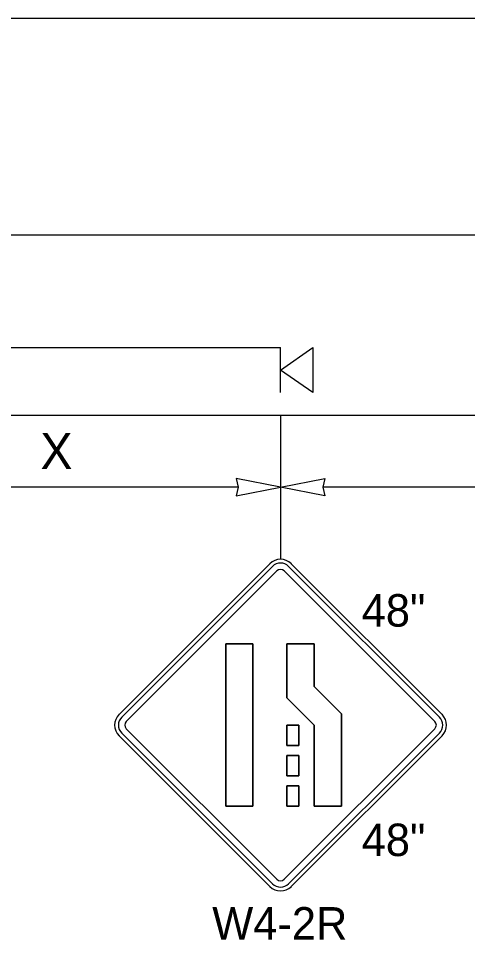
# Model space of a CAD drawing. Extents: x 99958 to 100176, y 99935 to 100011.
# Drawn here: x 100024.182 to 100025.178, y 99973.572 to 99975.616 of the extents above; entities that cross this region are included whole.
import ezdxf

# ---------------------------------------------------------------- set-up
doc = ezdxf.new("R2010")
doc.units = 0
for name, color, linetype in [('RD_ED_ShoulderPavedEdge', 7, 'Continuous'), ('RD_MK_LineEdgeWhite', 7, 'Continuous'), ('RD_MK_LineLane', 7, 'Continuous'), ('TR_SN_ConstructionSigns', 7, 'Continuous'), ('TR_WZ_PortableSignMountBlk-Org', 7, 'Continuous'), ('TR_WZ_WorkZoneDetails', 7, 'Continuous'), ('TR_WZ_WorkZoneTextCurrent', 7, 'Continuous')]:
    doc.layers.add(name, color=color, linetype=linetype)

msp = doc.modelspace()

# ---------------------------------------------------------------- linework, layer by layer
at = {"layer": 'RD_ED_ShoulderPavedEdge'}
msp.add_line((100021.7266, 99974.7357), (100034.8933, 99974.7357), dxfattribs=at)
at = {"layer": 'RD_MK_LineEdgeWhite'}
msp.add_line((100021.7266, 99975.1357), (100034.8933, 99975.1357), dxfattribs=at)
at = {"layer": 'RD_MK_LineLane'}
msp.add_lwpolyline([(100034.8933, 99975.6157), (100021.7266, 99975.6157)], dxfattribs=at)
at = {"layer": 'TR_SN_ConstructionSigns'}
for p, q in [((100024.7397, 99974.4058), (100024.4056, 99974.0717)), ((100024.7457, 99974.3999), (100024.4116, 99974.0658)), ((100025.1156, 99974.0658), (100024.7815, 99974.3999)), ((100025.1215, 99974.0717), (100024.7874, 99974.4058)), ((100024.4215, 99974.0558), (100024.7556, 99974.3899)), ((100024.7715, 99974.3899), (100025.1056, 99974.0558)), ((100024.6419, 99974.2279), (100024.7024, 99974.2279)), ((100024.6419, 99973.8679), (100024.6419, 99974.2279)), ((100024.7024, 99974.2279), (100024.6419, 99974.2279)), ((100024.6419, 99974.2279), (100024.6419, 99973.8679)), ((100024.7024, 99974.2279), (100024.7024, 99973.8679)), ((100024.7024, 99973.8679), (100024.7024, 99974.2279)), ((100024.7776, 99974.2279), (100024.8381, 99974.2279)), ((100024.7776, 99974.1083), (100024.7776, 99974.2279)), ((100024.8381, 99974.2279), (100024.7776, 99974.2279)), ((100024.7776, 99974.2279), (100024.7776, 99974.1083)), ((100024.8381, 99974.2279), (100024.8381, 99974.1334)), ((100024.8381, 99974.1334), (100024.8381, 99974.2279)), ((100024.8381, 99974.1334), (100024.8986, 99974.0729)), ((100024.8986, 99974.0729), (100024.8381, 99974.1334)), ((100024.8381, 99974.0479), (100024.7776, 99974.1083)), ((100024.7776, 99974.1083), (100024.8381, 99974.0479)), ((100024.8986, 99974.0729), (100024.8986, 99973.8679)), ((100024.8986, 99973.8679), (100024.8986, 99974.0729)), ((100024.7776, 99974.0479), (100024.8044, 99974.0479)), ((100024.7776, 99974.0029), (100024.7776, 99974.0479)), ((100024.8044, 99974.0479), (100024.7776, 99974.0479)), ((100024.7776, 99974.0479), (100024.7776, 99974.0029)), ((100024.8044, 99974.0479), (100024.8044, 99974.0029)), ((100024.8044, 99974.0029), (100024.8044, 99974.0479)), ((100024.8381, 99973.8679), (100024.8381, 99974.0479)), ((100024.8381, 99974.0479), (100024.8381, 99973.8679)), ((100024.4056, 99974.024), (100024.7397, 99973.6899)), ((100024.4116, 99974.03), (100024.7457, 99973.6959)), ((100024.7556, 99973.7058), (100024.4215, 99974.0399)), ((100025.1056, 99974.0399), (100024.7715, 99973.7058)), ((100024.7815, 99973.6959), (100025.1156, 99974.03)), ((100024.7874, 99973.6899), (100025.1215, 99974.024)), ((100024.8044, 99974.0029), (100024.7776, 99974.0029)), ((100024.7776, 99974.0029), (100024.8044, 99974.0029)), ((100024.7776, 99973.9804), (100024.8044, 99973.9804)), ((100024.7776, 99973.9354), (100024.7776, 99973.9804)), ((100024.8044, 99973.9804), (100024.7776, 99973.9804)), ((100024.7776, 99973.9804), (100024.7776, 99973.9354)), ((100024.8044, 99973.9804), (100024.8044, 99973.9354)), ((100024.8044, 99973.9354), (100024.8044, 99973.9804)), ((100024.8044, 99973.9354), (100024.7776, 99973.9354)), ((100024.7776, 99973.9354), (100024.8044, 99973.9354)), ((100024.7776, 99973.9129), (100024.8044, 99973.9129)), ((100024.7776, 99973.8679), (100024.7776, 99973.9129)), ((100024.8044, 99973.9129), (100024.7776, 99973.9129)), ((100024.7776, 99973.9129), (100024.7776, 99973.8679)), ((100024.8044, 99973.9129), (100024.8044, 99973.8679)), ((100024.8044, 99973.8679), (100024.8044, 99973.9129)), ((100024.7024, 99973.8679), (100024.6419, 99973.8679)), ((100024.6419, 99973.8679), (100024.7024, 99973.8679)), ((100024.8044, 99973.8679), (100024.7776, 99973.8679)), ((100024.7776, 99973.8679), (100024.8044, 99973.8679)), ((100024.8986, 99973.8679), (100024.8381, 99973.8679)), ((100024.8381, 99973.8679), (100024.8986, 99973.8679))]:
    msp.add_line(p, q, dxfattribs=at)
for centre, radius, start, end in [((100024.7636, 99974.382), 0.0338, 45, 135), ((100024.7636, 99974.382), 0.0253, 45, 135), ((100024.7636, 99974.382), 0.0113, 45, 135), ((100024.4295, 99974.0479), 0.0338, 135, 225), ((100024.4295, 99974.0479), 0.0253, 135, 225), ((100025.0977, 99974.0479), 0.0253, 315, 45), ((100025.0977, 99974.0479), 0.0338, 315, 45), ((100024.4295, 99974.0479), 0.0113, 135, 225), ((100025.0977, 99974.0479), 0.0113, 315, 45), ((100024.7636, 99973.7138), 0.0113, 225, 315), ((100024.7636, 99973.7138), 0.0338, 225, 315), ((100024.7636, 99973.7138), 0.0253, 225, 315)]:
    msp.add_arc(centre, radius, start, end, dxfattribs=at)
at = {"layer": 'TR_WZ_PortableSignMountBlk-Org'}
msp.add_line((100024.7636, 99974.7858), (100024.7636, 99974.8858), dxfattribs=at)
msp.add_lwpolyline([(100024.7636, 99974.8357), (100024.8354, 99974.8858), (100024.8354, 99974.7858)], close=True, dxfattribs=at)
at = {"layer": 'TR_WZ_WorkZoneDetails'}
for p, q in [((100022.1636, 99974.8858), (100024.7636, 99974.8858)), ((100024.7636, 99974.736), (100024.7636, 99974.4157)), ((100024.6698, 99974.5757), (100023.8573, 99974.5757)), ((100025.6698, 99974.5757), (100024.8573, 99974.5757))]:
    msp.add_line(p, q, dxfattribs=at)
for points in [[(100024.7636, 99974.5757), (100024.6653, 99974.595), (100024.6698, 99974.5757), (100024.6653, 99974.5565)], [(100024.7636, 99974.5757), (100024.8619, 99974.595), (100024.8573, 99974.5757), (100024.8619, 99974.5565)]]:
    msp.add_lwpolyline(points, close=True, dxfattribs=at)

# ---------------------------------------------------------------- texts
at = {"layer": 'TR_SN_ConstructionSigns'}
for s, p in [('48"', (100024.9434, 99974.2664)), ('48"', (100024.9434, 99973.7573)), ('W4-2R', (100024.6121, 99973.572))]:
    msp.add_text(s, height=0.072, rotation=360, dxfattribs=at).set_placement(p)
at = {"layer": 'TR_WZ_WorkZoneTextCurrent'}
msp.add_text('X', height=0.08, rotation=360, dxfattribs=at).set_placement((100024.2311, 99974.6157))

doc.saveas('drawing.dxf')
